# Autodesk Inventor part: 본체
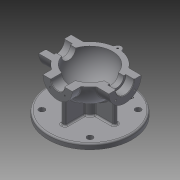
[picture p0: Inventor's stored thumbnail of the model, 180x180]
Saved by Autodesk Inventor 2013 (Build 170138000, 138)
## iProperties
Created: 2015-12
Part Number: 본체
Material: 일반
Document SubType Name: Modeling
Designer: mduedu
Density: 2.71 g/cm^3
Author: mduedu
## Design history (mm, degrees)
sketch "스케치1"
  geometry: L1 (-53, 0)-(53, 0); A1 r 53 centre (0, 0) between (53, 0) and (-53, 0); 2 further points
  constraints: 2 coincident, 2 end point, 2 point on circle, 1 centre point, 1 horizontal, 1 midpoint
  dimensions: "d0" = 53 radius of A1
revolve "회전1" sketch "스케치1" stored, may be unused: angle "d2" = 90 deg
feature "쉘1" dims "d11" = 10
node "작업 평면1"
sketch "스케치2"
  geometry: C1 r 31 at (0, 0); 1 further point
  constraints: 1 centre point, 1 coincident
  dimensions: "d4" = 62 diameter of C1
extrude "돌출1" join sketch "스케치2" stored distance "d5" = 10; taper "d6" = 0 deg
node "작업 평면2"
sketch "스케치3"
  geometry: C1 r 28 at (0, 0); 1 further point
  constraints: 1 centre point, 1 coincident
  dimensions: "d8" = 56 diameter of C1
extrude "돌출2" join sketch "스케치3" stored distance "d9" = 10; taper "d10" = 0 deg
hole "구멍1" diameter "d14" = 35; stored, may be unused: countersink angle "d18" = 90 deg, drill point angle "d20" = 0 deg; dims "d12" = 10, "d13" = 10, "d15" = 6, "d16" = 4, "d17" = 2, "d19" = 16
hole "구멍2" diameter "d23" = 27; stored, may be unused: countersink angle "d27" = 90 deg, drill point angle "d29" = 0 deg; dims "d21" = 10, "d22" = 10, "d24" = 6, "d25" = 4, "d26" = 2, "d28" = 16
fillet "모깎기1" dims "d30" = 0.3
hole "구멍3" diameter "d33" = 26; stored, may be unused: countersink angle "d37" = 90 deg, drill point angle "d39" = 0 deg; dims "d31" = 10, "d32" = 10, "d34" = 6, "d35" = 4, "d36" = 2, "d38" = 16
chamfer "모따기1" distance "d40" = 1; stored, may be unused: second distance "d41" = 2, angle "d42" = 45 deg
sketch "스케치4"
  geometry: L1 (0, 0)-(0, -25); L2 (0, 0)-(-17.678, -17.678); A1 r 25 centre (0, 0) between (-17.678, -17.678) and (0, -25); 1 further point
  constraints: 4 end point, 2 point on circle, 1 centre point, 1 coincident, 1 vertical
  dimensions: "d43" = 50 diameter of A1; "d47" = 45 deg angle of L1 L2
hole "구멍4" sketch "스케치4" at (-17.678, -17.678) diameter "d49" = 3.242; stored, may be unused: countersink angle "d53" = 90 deg, drill point angle "d55" = 118 deg; dims "d50" = 11, "d51" = 4, "d52" = 2, "d54" = 13
sketch "스케치5"
  geometry: L1 (0, 0)-(0, -20); L2 (0, 0)-(-14.142, -14.142); A1 r 20 centre (0, 0) between (0, -20) and (-14.142, -14.142); 2 further points
  constraints: 4 end point, 2 coincident, 2 point on circle, 1 centre point, 1 vertical
  dimensions: "d59" = 40 diameter of A1; "d65" = 45 deg angle of L1 L2
hole "구멍5" sketch "스케치5" at (-14.142, -14.142) diameter "d67" = 3.242; stored, may be unused: countersink angle "d71" = 90 deg, drill point angle "d73" = 118 deg; dims "d68" = 8, "d69" = 4, "d70" = 2, "d72" = 10
node "작업 평면3"
sketch "스케치6"
  geometry: C1 r 80 at (0, 0); 1 further point
  constraints: 1 centre point, 1 coincident
  dimensions: "d78" = 160 diameter of C1
extrude "돌출3" join sketch "스케치6" distance "d80" = 10; taper "d81" = 0 deg
sketch "스케치7"
  geometry: C1 r 15 at (0, 0); 1 further point
  constraints: 1 centre point, 1 coincident
  dimensions: "d82" = 30 diameter of C1
extrude "돌출4" join sketch "스케치7" stored distance "d84" = 10; taper "d85" = 0 deg
sketch "스케치8"
  geometry: 2 further points
  constraints: 1 coincident
hole "구멍6" sketch "스케치8" at (0, 0) diameter "d86" = 20; stored, may be unused: countersink angle "d90" = 90 deg, drill point angle "d92" = 118 deg; dims "d87" = 7, "d88" = 100, "d89" = 5, "d91" = 10
fillet "모깎기2" dims "d93" = 0.3
sketch "스케치9"
  geometry: L1 (-67, -18.5)-(-66, -17.5) reference; L2 (-66, -17.5)-(-51.3, -17.5) reference; L3 (-51, -17.2)-(-51, -13.5) reference; L4 (-51, -13.5)-(-40.826, -13.5) reference; L5 (-10, -41.821)-(-10, -80) reference; L6 (-10, -80)-(-49.7, -80) reference; L7 (-50, -80.3)-(-50, -85) reference; L8 (-50, -85)-(-80, -85) reference; L9 (-80, -85)-(-80, -75) reference; L10 (-80, -75)-(-15, -75) reference; L11 (-15, -75)-(-15, -50.833) reference; L12 (-42.988, -31)-(-67, -31) reference; L13 (-67, -31)-(-67, -18.5) reference; L14 (66, -17.5)-(67, -18.5) reference; L15 (67, -18.5)-(67, -31) reference; L16 (67, -31)-(42.988, -31) reference; L17 (15, -50.833)-(15, -75) reference; L18 (15, -75)-(80, -75) reference; L19 (80, -75)-(80, -85) reference; L20 (80, -85)-(50, -85) reference; L21 (50, -85)-(50, -80.3) reference; L22 (49.7, -80)-(10, -80) reference; L23 (10, -80)-(10, -41.821) reference; L24 (40.826, -13.5)-(51, -13.5) reference; L25 (51, -13.5)-(51, -17.2) reference; L26 (51.3, -17.5)-(66, -17.5) reference; L27 (67, 18.5)-(66, 17.5) reference; L28 (66, 17.5)-(51.3, 17.5) reference; L29 (51, 17.2)-(51, 13.5) reference; L30 (51, 13.5)-(40.826, 13.5) reference; L31 (-40.826, 13.5)-(-51, 13.5) reference; L32 (-51, 13.5)-(-51, 17.2) reference; L33 (-51.3, 17.5)-(-66, 17.5) reference; L34 (-66, 17.5)-(-67, 18.5) reference; L35 (-67, 18.5)-(-67, 31) reference; L36 (-67, 31)-(-42.988, 31) reference; L37 (42.988, 31)-(67, 31) reference; L38 (67, 31)-(67, 18.5) reference; L39 (-50, -31)-(-50, -75); A1 r 0.3 centre (-51.3, -17.2) between (-51.3, -17.5) and (-51, -17.2) reference; A2 r 43 centre (0, 0) between (-40.826, -13.5) and (-10, -41.821) reference; A3 r 0.3 centre (-49.7, -80.3) between (-49.7, -80) and (-50, -80.3) reference; A4 r 53 centre (0, 0) between (-42.988, -31) and (-15, -50.833) reference; A5 r 53 centre (0, 0) between (15, -50.833) and (42.988, -31) reference; A6 r 0.3 centre (49.7, -80.3) between (50, -80.3) and (49.7, -80) reference; A7 r 43 centre (0, 0) between (10, -41.821) and (40.826, -13.5) reference; A8 r 0.3 centre (51.3, -17.2) between (51, -17.2) and (51.3, -17.5) reference; A9 r 0.3 centre (51.3, 17.2) between (51.3, 17.5) and (51, 17.2) reference; A10 r 43 centre (0, 0) between (40.826, 13.5) and (-40.826, 13.5) reference; A11 r 0.3 centre (-51.3, 17.2) between (-51, 17.2) and (-51.3, 17.5) reference; A12 r 53 centre (0, 0) between (42.988, 31) and (-42.988, 31) reference; 1 further point
  constraints: 2 end point, 2 point on line
  dimensions: "d173" = 30 distance from line of L39.end L9; "d174" = 90 deg angle of L10 L39
feature "리브1" sketch "스케치9" dims "d96" = 1, "d97" = 8, "d98" = 0, "d99" = 0, "d100" = 1, "d101" = 1
sketch "스케치14"
  geometry: L1 (-14, 62)-(-13, 61) reference; L2 (-13, 61)-(-13, 40.988) reference; L3 (-41.821, 10)-(-80, 10) reference; L4 (-80, 10)-(-80, 49.7) reference; L5 (-80.3, 50)-(-85, 50) reference; L6 (-85, 50)-(-85, 80) reference; L7 (-85, 80)-(-75, 80) reference; L8 (-75, 80)-(-75, 15) reference; L9 (-75, 15)-(-50.833, 15) reference; L10 (-28, 45)-(-28, 62) reference; L11 (-28, 62)-(-14, 62) reference; L12 (13, 61)-(14, 62) reference; L13 (14, 62)-(28, 62) reference; L14 (28, 62)-(28, 45) reference; L15 (-50.833, -15)-(-75, -15) reference; L16 (-75, -15)-(-75, -80) reference; L17 (-75, -80)-(-85, -80) reference; L18 (-85, -80)-(-85, -50) reference; L19 (-85, -50)-(-80.3, -50) reference; L20 (-80, -49.7)-(-80, -10) reference; L21 (-80, -10)-(-41.821, -10) reference; L22 (13, 40.988)-(13, 61) reference; L23 (-28, 52)-(-75, 52); A1 r 43 centre (0, 0) between (-13, 40.988) and (-41.821, 10) reference; A2 r 0.3 centre (-80.3, 49.7) between (-80, 49.7) and (-80.3, 50) reference; A3 r 53 centre (0, 0) between (-28, 45) and (-50.833, 15) reference; A4 r 53 centre (0, 0) between (0, -53) and (28, 45) reference; A5 r 53 centre (0, 0) between (-50.833, -15) and (0, -53) reference; A6 r 0.3 centre (-80.3, -49.7) between (-80.3, -50) and (-80, -49.7) reference; A7 r 43 centre (0, 0) between (-41.821, -10) and (0, -43) reference; A8 r 43 centre (0, 0) between (0, -43) and (13, 40.988) reference; 1 further point
  constraints: 2 end point, 2 point on line
  dimensions: "d175" = 28 distance of L7.end L23.end; "d176" = 90 deg angle of L8 L23
feature "리브2" sketch "스케치14" dims "d153" = 1, "d154" = 8, "d155" = 0, "d156" = 0, "d157" = 1, "d158" = 1
sketch "스케치10"
  geometry: L1 (0, 0)-(0, -65); L2 (0, 0)-(-45.962, -45.962); A1 r 65 centre (0, 0) between (0, -65) and (-45.962, -45.962); 2 further points
  constraints: 4 end point, 2 coincident, 2 point on circle, 1 centre point, 1 vertical
  dimensions: "d105" = 130 diameter of A1; "d107" = 45 deg angle of L1 L2
hole "구멍7" sketch "스케치10" at (-45.962, -45.962) diameter "d109" = 11; stored, may be unused: countersink angle "d113" = 90 deg, drill point angle "d115" = 118 deg; dims "d110" = 7, "d111" = 18, "d112" = 4, "d114" = 10
fillet "모깎기3" dims "d120" = 3
fillet "모깎기4" dims "d121" = 3, "d122" = 3
fillet "모깎기5" dims "d123" = 3
fillet "모깎기6" dims "d124" = 3
sketch "스케치11"
  geometry: C1 r 80 at (0, 0) reference; C2 r 65 at (0, 0)
  constraints: 1 centre point, 1 coincident, 1 other
  dimensions: "d161" = 130 diameter of C2
feature "엠보싱1" sketch "스케치11" dims "d11" = 10, "d125" = 0.5, "d126" = 0
sketch "스케치12"
  geometry: L1 (0, 100)-(0, -100); L2 (0, 100)-(100, 100); L3 (100, 100)-(100, -100); L4 (100, -100)-(0, -100); 2 further points
  constraints: 8 end point, 3 perpendicular, 1 coincident, 1 midpoint, 1 vertical
  dimensions: "d127" = 200 distance of L2.end L3.end; "d129" = 100 distance between parallel lines of L1 L3
extrude "돌출5" cut sketch "스케치12" stored distance "d130" = 10; taper "d131" = 0 deg
sketch "스케치13"
  geometry: C1 r 7 at (0, 53); A1 r 53 centre (0, 0) between (42.113, 32.179) and (-42.113, 32.179) reference; 1 further point
  constraints: 1 centre point, 1 point on circle
  dimensions: "d132" = 14 diameter of C1
extrude "돌출6" join sketch "스케치13" distance "d134" = 15; taper "d135" = 0 deg
hole "구멍8" diameter "d139" = 3.242; stored, may be unused: countersink angle "d143" = 90 deg, drill point angle "d145" = 118 deg; dims "d140" = 8, "d141" = 4, "d142" = 2, "d144" = 10, "d148" = 10, "d149" = 10
fillet "모깎기7" dims "d146" = 3
fillet "모깎기8" dims "d147" = 3
node "솔리드1"
mirror "대칭1"
mirror "대칭2"
pattern_circular "원형 패턴1" dims angle "d57" = 360 deg
mirror "대칭3"
pattern_circular "원형 패턴2" dims angle "d75" = 360 deg
mirror "대칭4"
pattern_circular "원형 패턴4" dims angle "d118" = 360 deg
node "절단 모서리 투영1"
node "절단 모서리 투영2"
other parameters: "d3" = 67, "d7" = 62, "d77" = -85
